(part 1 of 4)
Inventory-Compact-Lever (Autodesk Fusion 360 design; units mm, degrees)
parameter "FrameLength" = 640 comment "Fixed existing outer length"
parameter "FrameWidth" = 190 comment "Fixed existing outer width"
parameter "FrameHeight" = 110 comment "Fixed existing height"
parameter "PivotHeight" = 65 comment "Above frame center"
parameter "LeverTravel" = 100 comment "Stable endpoint to endpoint"
parameter "PrintClearance" = 0.3 comment "Prototype diametral running clearance"
base_mesh_feature "Base Mesh Feature"
ground "Pin1"
work_plane "WorkPlane1" AlongDistance -36 ExtraOffset 0
sketch "Flat load-bearing plate" plane through (-36, 0, 0) normal (1, 0, 0) x axis (0, 0, -1)
  line L1 (-33, -55) -> (-33, -75)
  line L2 (2, -55) -> (-33, -55)
  line L3 (2, 55) -> (2, -55)
  line L4 (-33, 55) -> (2, 55)
  line L5 (-33, 75) -> (-33, 55)
  line L6 (-57, 75) -> (-33, 75)
  line L7 (-57, 32) -> (-57, 75)
  line L8 (-86, 26) -> (-57, 32)
  line L9 (-86, -26) -> (-86, 26)
  line L10 (-57, -32) -> (-86, -26)
  line L11 (-57, -75) -> (-57, -32)
  line L12 (-33, -75) -> (-57, -75)
extrude "Extrude1" new body sketch "Flat load-bearing plate" along normal blind 12
work_plane "WorkPlane2" AlongDistance -37 ExtraOffset 0
sketch "Replaceable bushing seat" plane through (-37, 0, 0) normal (1, 0, 0) x axis (0, 0, -1)
  circle C1 centre (-65, 0) radius 10.15
extrude "Extrude2" cut sketch "Replaceable bushing seat" along normal blind 14
work_plane "WorkPlane3" AlongDistance -37 ExtraOffset 0
sketch "Follower pivot bolt" plane through (-37, 0, 0) normal (1, 0, 0) x axis (0, 0, -1)
  circle C1 centre (-12, -35) radius 2.7
extrude "Extrude3" cut sketch "Follower pivot bolt" along normal blind 14
work_plane "WorkPlane4" AlongDistance -76 ExtraOffset 0
sketch "M5 rail mounting bore" plane through (0, -76, 0) normal (0, 1, 0) x axis (1, 0, 0)
  circle C1 centre (-30, -45) radius 2.7
extrude "Extrude4" cut sketch "M5 rail mounting bore" along normal blind 22
work_plane "WorkPlane5" AlongDistance -55 ExtraOffset 0
sketch "Rail screw tool and washer access" plane through (0, -55, 0) normal (0, 1, 0) x axis (1, 0, 0)
  circle C1 centre (-30, -45) radius 5.3
extrude "Extrude5" cut sketch "Rail screw tool and washer access" along normal blind 12
work_plane "WorkPlane6" AlongDistance 54 ExtraOffset 0
sketch "M5 rail mounting bore (1)" plane through (0, 54, 0) normal (0, 1, 0) x axis (1, 0, 0)
  circle C1 centre (-30, -45) radius 2.7
extrude "Extrude6" cut sketch "M5 rail mounting bore (1)" along normal blind 22
work_plane "WorkPlane7" AlongDistance 43 ExtraOffset 0
sketch "Rail screw tool and washer access (1)" plane through (0, 43, 0) normal (0, 1, 0) x axis (1, 0, 0)
  circle C1 centre (-30, -45) radius 5.3
extrude "Extrude7" cut sketch "Rail screw tool and washer access (1)" along normal blind 12
work_plane "WorkPlane8" AlongDistance -37 ExtraOffset 0
sketch "Spring crossblock attachment" plane through (-37, 0, 0) normal (1, 0, 0) x axis (0, 0, -1)
  circle C1 centre (-44, -59) radius 1.7
extrude "Extrude8" cut sketch "Spring crossblock attachment" along normal blind 14
work_plane "WorkPlane9" AlongDistance -37 ExtraOffset 0
sketch "Spring crossblock attachment (1)" plane through (-37, 0, 0) normal (1, 0, 0) x axis (0, 0, -1)
  circle C1 centre (-44, -51) radius 1.7
extrude "Extrude9" cut sketch "Spring crossblock attachment (1)" along normal blind 14
work_plane "WorkPlane1" AlongDistance 24 ExtraOffset 0
sketch "Flat load-bearing plate" plane through (24, 0, 0) normal (1, 0, 0) x axis (0, 0, -1)
  line L1 (-33, -55) -> (-33, -75)
  line L2 (2, -55) -> (-33, -55)
  line L3 (2, 55) -> (2, -55)
  line L4 (-33, 55) -> (2, 55)
  line L5 (-33, 75) -> (-33, 55)
  line L6 (-57, 75) -> (-33, 75)
  line L7 (-57, 32) -> (-57, 75)
  line L8 (-86, 26) -> (-57, 32)
  line L9 (-86, -26) -> (-86, 26)
  line L10 (-57, -32) -> (-86, -26)
  line L11 (-57, -75) -> (-57, -32)
  line L12 (-33, -75) -> (-57, -75)
extrude "Extrude1" new body sketch "Flat load-bearing plate" along normal blind 12
work_plane "WorkPlane2" AlongDistance 23 ExtraOffset 0
sketch "Replaceable bushing seat" plane through (23, 0, 0) normal (1, 0, 0) x axis (0, 0, -1)
  circle C1 centre (-65, 0) radius 10.15
extrude "Extrude2" cut sketch "Replaceable bushing seat" along normal blind 14
work_plane "WorkPlane3" AlongDistance 23 ExtraOffset 0
sketch "Follower pivot bolt" plane through (23, 0, 0) normal (1, 0, 0) x axis (0, 0, -1)
  circle C1 centre (-12, -35) radius 2.7
extrude "Extrude3" cut sketch "Follower pivot bolt" along normal blind 14
work_plane "WorkPlane4" AlongDistance -76 ExtraOffset 0
sketch "M5 rail mounting bore" plane through (0, -76, 0) normal (0, 1, 0) x axis (1, 0, 0)
  circle C1 centre (30, -45) radius 2.7
extrude "Extrude4" cut sketch "M5 rail mounting bore" along normal blind 22
work_plane "WorkPlane5" AlongDistance -55 ExtraOffset 0
sketch "Rail screw tool and washer access" plane through (0, -55, 0) normal (0, 1, 0) x axis (1, 0, 0)
  circle C1 centre (30, -45) radius 5.3
extrude "Extrude5" cut sketch "Rail screw tool and washer access" along normal blind 12
work_plane "WorkPlane6" AlongDistance 54 ExtraOffset 0
sketch "M5 rail mounting bore (1)" plane through (0, 54, 0) normal (0, 1, 0) x axis (1, 0, 0)
  circle C1 centre (30, -45) radius 2.7
extrude "Extrude6" cut sketch "M5 rail mounting bore (1)" along normal blind 22
work_plane "WorkPlane7" AlongDistance 43 ExtraOffset 0
sketch "Rail screw tool and washer access (1)" plane through (0, 43, 0) normal (0, 1, 0) x axis (1, 0, 0)
  circle C1 centre (30, -45) radius 5.3
extrude "Extrude7" cut sketch "Rail screw tool and washer access (1)" along normal blind 12
work_plane "WorkPlane8" AlongDistance 23 ExtraOffset 0
sketch "Spring crossblock attachment" plane through (23, 0, 0) normal (1, 0, 0) x axis (0, 0, -1)
  circle C1 centre (-44, -59) radius 1.7
extrude "Extrude8" cut sketch "Spring crossblock attachment" along normal blind 14
work_plane "WorkPlane9" AlongDistance 23 ExtraOffset 0
sketch "Spring crossblock attachment (1)" plane through (23, 0, 0) normal (1, 0, 0) x axis (0, 0, -1)
  circle C1 centre (-44, -51) radius 1.7
extrude "Extrude9" cut sketch "Spring crossblock attachment (1)" along normal blind 14
work_plane "WorkPlane1" AlongDistance -36 ExtraOffset 0
sketch "Replaceable journal body" plane through (-36, 0, 0) normal (1, 0, 0) x axis (0, 0, -1)
  circle C1 centre (-65, 0) radius 10.05
extrude "Extrude1" new body sketch "Replaceable journal body" along normal blind 12 bodies "P03 Left flanged journal bush"
work_plane "WorkPlane2" AlongDistance -37.2 ExtraOffset 0
sketch "Axial thrust flange" plane through (-37.2, 0, 0) normal (1, 0, 0) x axis (0, 0, -1)
  circle C1 centre (-65, 0) radius 12.75
extrude "Extrude2" add sketch "Axial thrust flange" along normal blind 1.2
work_plane "WorkPlane3" AlongDistance -38 ExtraOffset 0
sketch "Running journal bore" plane through (-38, 0, 0) normal (1, 0, 0) x axis (0, 0, -1)
  circle C1 centre (-65, 0) radius 6.15
extrude "Extrude3" cut sketch "Running journal bore" along normal blind 15
work_plane "WorkPlane1" AlongDistance 24 ExtraOffset 0
sketch "Replaceable journal body" plane through (24, 0, 0) normal (1, 0, 0) x axis (0, 0, -1)
  circle C1 centre (-65, 0) radius 10.05
extrude "Extrude1" new body sketch "Replaceable journal body" along normal blind 12 bodies "P04 Right flanged journal bush"
work_plane "WorkPlane2" AlongDistance 36 ExtraOffset 0
sketch "Axial thrust flange" plane through (36, 0, 0) normal (1, 0, 0) x axis (0, 0, -1)
  circle C1 centre (-65, 0) radius 12.75
extrude "Extrude2" add sketch "Axial thrust flange" along normal blind 1.2
work_plane "WorkPlane3" AlongDistance 23 ExtraOffset 0
sketch "Running journal bore" plane through (23, 0, 0) normal (1, 0, 0) x axis (0, 0, -1)
  circle C1 centre (-65, 0) radius 6.15
extrude "Extrude3" cut sketch "Running journal bore" along normal blind 15
work_plane "WorkPlane1" AlongDistance -37.35 ExtraOffset 0
sketch "Continuous 12 mm journals" plane through (-37.35, 0, 0) normal (1, 0, 0) x axis (0, 0, -1)
  circle C1 centre (-65, 0) radius 6
extrude "Extrude1" new body sketch "Continuous 12 mm journals" along normal blind 74.7 bodies "P05 Shaft lower half"
work_plane "WorkPlane2" AlongDistance -23.8 ExtraOffset 0
sketch "16 mm structural shaft" plane through (-23.8, 0, 0) normal (1, 0, 0) x axis (0, 0, -1)
  circle C1 centre (-65, 0) radius 8
extrude "Extrude2" add sketch "16 mm structural shaft" along normal blind 47.6
work_plane "WorkPlane3" AlongDistance -23.9 ExtraOffset 0
sketch "D-flat torque key" plane through (-23.9, 0, 0) normal (1, 0, 0) x axis (0, 0, -1)
  line L1 (-56, 9) -> (-56, 6.5)
  line L2 (-74, 9) -> (-56, 9)
  line L3 (-74, 6.5) -> (-74, 9)
  line L4 (-56, 6.5) -> (-74, 6.5)
extrude "Extrude3" cut sketch "D-flat torque key" along normal blind 47.8
work_plane "WorkPlane4" AlongDistance 37.35 ExtraOffset 0
sketch "Integral axial shoulder" plane through (37.35, 0, 0) normal (1, 0, 0) x axis (0, 0, -1)
  circle C1 centre (-65, 0) radius 10
extrude "Extrude4" add sketch "Integral axial shoulder" along normal blind 3
work_plane "WorkPlane5" AlongDistance 40.35 ExtraOffset 0
sketch "Sensor drive stub" plane through (40.35, 0, 0) normal (1, 0, 0) x axis (0, 0, -1)
  circle C1 centre (-65, 0) radius 4
extrude "Extrude5" add sketch "Sensor drive stub" along normal blind 10
work_plane "WorkPlane6" AlongDistance 40.25 ExtraOffset 0
sketch "Sensor drive flat" plane through (40.25, 0, 0) normal (1, 0, 0) x axis (0, 0, -1)
  line L1 (-60, 5) -> (-60, 3.2)
  line L2 (-70, 5) -> (-60, 5)
  line L3 (-70, 3.2) -> (-70, 5)
  line L4 (-60, 3.2) -> (-70, 3.2)
extrude "Extrude6" cut sketch "Sensor drive flat" along normal blind 10.25
work_plane "WorkPlane7" AlongDistance -37.45 ExtraOffset 0
sketch "M3 heat-set end retention" plane through (-37.45, 0, 0) normal (1, 0, 0) x axis (0, 0, -1)
  circle C1 centre (-65, 0) radius 2
extrude "Extrude7" cut sketch "M3 heat-set end retention" along normal blind 6.8
work_plane "WorkPlane1" AlongDistance -39.35 ExtraOffset 0
sketch "Axial cap" plane through (-39.35, 0, 0) normal (1, 0, 0) x axis (0, 0, -1)
  circle C1 centre (-65, 0) radius 10
extrude "Extrude1" new body sketch "Axial cap" along normal blind 2 bodies "P06 Shaft retaining cap"
work_plane "WorkPlane2" AlongDistance -39.5 ExtraOffset 0
sketch "M3 cap screw" plane through (-39.5, 0, 0) normal (1, 0, 0) x axis (0, 0, -1)
  circle C1 centre (-65, 0) radius 1.7
extrude "Extrude2" cut sketch "M3 cap screw" along normal blind 2.4
work_plane "WorkPlane1" AlongDistance -7 ExtraOffset 0
sketch "Main lever hub" plane through (-7, 0, 0) normal (1, 0, 0) x axis (0, 0, -1)
  circle C1 centre (-65, 0) radius 22
extrude "Extrude1" new body sketch "Main lever hub" along normal blind 14 bodies "P07 Integral lever rotor and cam carrier"
work_plane "WorkPlane2" AlongDistance -7 ExtraOffset 0
sketch "Continuous reinforced lever stem" plane through (-7, 0, 0) normal (1, 0, 0) x axis (0, 0, -1)
  line L1 (-60, 14) -> (-60, -14)
  line L2 (-95, 11) -> (-60, 14)
  line L3 (-150, 7) -> (-95, 11)
  line L4 (-195, 7) -> (-150, 7)
  line L5 (-195, -7) -> (-195, 7)
  line L6 (-150, -7) -> (-195, -7)
  line L7 (-95, -11) -> (-150, -7)
  line L8 (-60, -14) -> (-95, -11)
extrude "Extrude2" add sketch "Continuous reinforced lever stem" along normal blind 14
work_plane "WorkPlane3" AlongDistance -7 ExtraOffset 0
sketch "Integrated cam carrier fan" plane through (-7, 0, 0) normal (1, 0, 0) x axis (0, 0, -1)
  line L1 (-44.5, 35.507) -> (-65, 0)
  line L2 (-42.6698, 34.3855) -> (-44.5, 35.507)
  line L3 (-40.9008, 33.1697) -> (-42.6698, 34.3855)
  line L4 (-39.1979, 31.863) -> (-40.9008, 33.1697)
  line L5 (-37.5656, 30.4689) -> (-39.1979, 31.863)
  line L6 (-36.0086, 28.9914) -> (-37.5656, 30.4689)
  line L7 (-34.5311, 27.4344) -> (-36.0086, 28.9914)
  line L8 (-33.137, 25.8021) -> (-34.5311, 27.4344)
  line L9 (-31.8303, 24.0992) -> (-33.137, 25.8021)
  line L10 (-30.6145, 22.3302) -> (-31.8303, 24.0992)
  line L11 (-29.493, 20.5) -> (-30.6145, 22.3302)
  line L12 (-28.4687, 18.6136) -> (-29.493, 20.5)
  line L13 (-27.5446, 16.6762) -> (-28.4687, 18.6136)
  line L14 (-26.7232, 14.6931) -> (-27.5446, 16.6762)
  line L15 (-26.0067, 12.6697) -> (-26.7232, 14.6931)
  line L16 (-25.397, 10.6116) -> (-26.0067, 12.6697)
  line L17 (-24.8959, 8.5244) -> (-25.397, 10.6116)
  line L18 (-24.5048, 6.4138) -> (-24.8959, 8.5244)
  line L19 (-24.2246, 4.2857) -> (-24.5048, 6.4138)
  line L20 (-24.0562, 2.1458) -> (-24.2246, 4.2857)
  line L21 (-24, 0) -> (-24.0562, 2.1458)
  line L22 (-24.0562, -2.1458) -> (-24, 0)
  line L23 (-24.2246, -4.2857) -> (-24.0562, -2.1458)
  line L24 (-24.5048, -6.4138) -> (-24.2246, -4.2857)
  line L25 (-24.8959, -8.5244) -> (-24.5048, -6.4138)
  line L26 (-25.397, -10.6116) -> (-24.8959, -8.5244)
  line L27 (-26.0067, -12.6697) -> (-25.397, -10.6116)
  line L28 (-26.7232, -14.6931) -> (-26.0067, -12.6697)
  line L29 (-27.5446, -16.6762) -> (-26.7232, -14.6931)
  line L30 (-28.4687, -18.6136) -> (-27.5446, -16.6762)
  line L31 (-29.493, -20.5) -> (-28.4687, -18.6136)
  line L32 (-30.6145, -22.3302) -> (-29.493, -20.5)
  line L33 (-31.8303, -24.0992) -> (-30.6145, -22.3302)
  line L34 (-33.137, -25.8021) -> (-31.8303, -24.0992)
  line L35 (-34.5311, -27.4344) -> (-33.137, -25.8021)
  line L36 (-36.0086, -28.9914) -> (-34.5311, -27.4344)
  line L37 (-37.5656, -30.4689) -> (-36.0086, -28.9914)
  line L38 (-39.1979, -31.863) -> (-37.5656, -30.4689)
  line L39 (-40.9008, -33.1697) -> (-39.1979, -31.863)
  line L40 (-42.6698, -34.3855) -> (-40.9008, -33.1697)
  line L41 (-44.5, -35.507) -> (-42.6698, -34.3855)
  line L42 (-65, 0) -> (-44.5, -35.507)
extrude "Extrude3" add sketch "Integrated cam carrier fan" along normal blind 14
work_plane "WorkPlane4" AlongDistance -23.6 ExtraOffset 0
sketch "Integral axial locating hub" plane through (-23.6, 0, 0) normal (1, 0, 0) x axis (0, 0, -1)
  circle C1 centre (-65, 0) radius 10
work_plane "WorkPlane5" AlongDistance -24 ExtraOffset 0
sketch "D shaft socket" plane through (-24, 0, 0) normal (1, 0, 0) x axis (0, 0, -1)
  line L1 (-69.6247, 6.65) -> (-60.3753, 6.65)
  arc A1 centre (-65, 0) radius 8.1 clockwise from (-60.3753, 6.65) to (-69.6247, 6.65)
extrude "Extrude5" cut sketch "D shaft socket" along normal blind 48
work_plane "WorkPlane6" AlongDistance 0.3 ExtraOffset 0
sketch "Cam M3 insert pocket" plane through (0.3, 0, 0) normal (1, 0, 0) x axis (0, 0, -1)
  circle C1 centre (-39.5442, 25.4558) radius 2
extrude "Extrude6" cut sketch "Cam M3 insert pocket" along normal blind 6.8
work_plane "WorkPlane7" AlongDistance 0.3 ExtraOffset 0
sketch "Cam M3 insert pocket (1)" plane through (0.3, 0, 0) normal (1, 0, 0) x axis (0, 0, -1)
  circle C1 centre (-29, 0) radius 2
extrude "Extrude7" cut sketch "Cam M3 insert pocket (1)" along normal blind 6.8
work_plane "WorkPlane8" AlongDistance 0.3 ExtraOffset 0
sketch "Cam M3 insert pocket (2)" plane through (0.3, 0, 0) normal (1, 0, 0) x axis (0, 0, -1)
  circle C1 centre (-39.5442, -25.4558) radius 2
extrude "Extrude8" cut sketch "Cam M3 insert pocket (2)" along normal blind 6.8
work_plane "WorkPlane9" AlongDistance -8 ExtraOffset 0
sketch "Grip through bolt" plane through (-8, 0, 0) normal (1, 0, 0) x axis (0, 0, -1)
  circle C1 centre (-180, 0) radius 1.7
extrude "Extrude9" cut sketch "Grip through bolt" along normal blind 16
work_plane "WorkPlane10" AlongDistance -8 ExtraOffset 0
sketch "Grip through bolt (1)" plane through (-8, 0, 0) normal (1, 0, 0) x axis (0, 0, -1)
  circle C1 centre (-190, 0) radius 1.7
extrude "Extrude10" cut sketch "Grip through bolt (1)" along normal blind 16
work_plane "WorkPlane1" AlongDistance 7 ExtraOffset 0
sketch "Roller compensated replaceable cam" plane through (7, 0, 0) normal (1, 0, 0) x axis (0, 0, -1)
  line L1 (-39.4967, 42.2602) -> (-39.6212, 42.3096)
  line L2 (-39.3834, 42.211) -> (-39.4967, 42.2602)
  line L3 (-39.2796, 42.1617) -> (-39.3834, 42.211)
  line L4 (-39.1836, 42.1119) -> (-39.2796, 42.1617)
  line L5 (-39.0932, 42.0608) -> (-39.1836, 42.1119)
  line L6 (-39.0065, 42.0075) -> (-39.0932, 42.0608)
  line L7 (-38.9215, 41.9508) -> (-39.0065, 42.0075)
  line L8 (-38.8363, 41.8895) -> (-38.9215, 41.9508)
  line L9 (-38.7492, 41.8219) -> (-38.8363, 41.8895)
  line L10 (-38.6586, 41.7465) -> (-38.7492, 41.8219)
  line L11 (-38.5633, 41.6619) -> (-38.6586, 41.7465)
  line L12 (-38.4623, 41.5665) -> (-38.5633, 41.6619)
  line L13 (-38.3549, 41.459) -> (-38.4623, 41.5665)
  line L14 (-38.2404, 41.3384) -> (-38.3549, 41.459)
  line L15 (-38.1184, 41.204) -> (-38.2404, 41.3384)
  line L16 (-37.9886, 41.055) -> (-38.1184, 41.204)
  line L17 (-37.8508, 40.8913) -> (-37.9886, 41.055)
  line L18 (-37.7045, 40.7127) -> (-37.8508, 40.8913)
  line L19 (-37.5496, 40.5196) -> (-37.7045, 40.7127)
  line L20 (-37.3856, 40.3123) -> (-37.5496, 40.5196)
  line L21 (-37.2122, 40.0915) -> (-37.3856, 40.3123)
  line L22 (-37.0289, 39.858) -> (-37.2122, 40.0915)
  line L23 (-36.8353, 39.6128) -> (-37.0289, 39.858)
  line L24 (-36.6306, 39.3571) -> (-36.8353, 39.6128)
  line L25 (-36.4145, 39.0923) -> (-36.6306, 39.3571)
  line L26 (-36.1865, 38.82) -> (-36.4145, 39.0923)
  line L27 (-35.9461, 38.5417) -> (-36.1865, 38.82)
  line L28 (-35.6932, 38.2594) -> (-35.9461, 38.5417)
  line L29 (-35.4277, 37.9751) -> (-35.6932, 38.2594)
  line L30 (-35.15, 37.6908) -> (-35.4277, 37.9751)
  line L31 (-34.8607, 37.4087) -> (-35.15, 37.6908)
  line L32 (-34.5606, 37.1307) -> (-34.8607, 37.4087)
  line L33 (-34.2512, 36.859) -> (-34.5606, 37.1307)
  line L34 (-33.934, 36.5953) -> (-34.2512, 36.859)
  line L35 (-33.6109, 36.341) -> (-33.934, 36.5953)
  line L36 (-33.2841, 36.0975) -> (-33.6109, 36.341)
  line L37 (-32.9558, 35.8655) -> (-33.2841, 36.0975)
  line L38 (-32.6282, 35.6454) -> (-32.9558, 35.8655)
  line L39 (-32.3036, 35.4375) -> (-32.6282, 35.6454)
  line L40 (-31.984, 35.2415) -> (-32.3036, 35.4375)
  line L41 (-31.6712, 35.057) -> (-31.984, 35.2415)
  line L42 (-31.3671, 34.8833) -> (-31.6712, 35.057)
  line L43 (-31.073, 34.7197) -> (-31.3671, 34.8833)
  line L44 (-30.7902, 34.5655) -> (-31.073, 34.7197)
  line L45 (-30.52, 34.4197) -> (-30.7902, 34.5655)
  line L46 (-30.263, 34.2816) -> (-30.52, 34.4197)
  line L47 (-30.0201, 34.1506) -> (-30.263, 34.2816)
  line L48 (-29.7919, 34.0259) -> (-30.0201, 34.1506)
  line L49 (-29.5787, 33.9071) -> (-29.7919, 34.0259)
  line L50 (-29.3807, 33.7939) -> (-29.5787, 33.9071)
  line L51 (-29.1982, 33.6858) -> (-29.3807, 33.7939)
  line L52 (-29.0309, 33.5827) -> (-29.1982, 33.6858)
  line L53 (-28.8786, 33.4843) -> (-29.0309, 33.5827)
  line L54 (-28.7406, 33.3906) -> (-28.8786, 33.4843)
  line L55 (-28.6164, 33.3013) -> (-28.7406, 33.3906)
  line L56 (-28.5047, 33.2161) -> (-28.6164, 33.3013)
  line L57 (-28.4046, 33.1346) -> (-28.5047, 33.2161)
  line L58 (-28.3144, 33.0563) -> (-28.4046, 33.1346)
  line L59 (-28.2327, 32.9802) -> (-28.3144, 33.0563)
  line L60 (-28.1577, 32.9052) -> (-28.2327, 32.9802)
  line L61 (-28.0879, 32.8301) -> (-28.1577, 32.9052)
  line L62 (-28.0214, 32.7532) -> (-28.0879, 32.8301)
  line L63 (-27.9569, 32.6728) -> (-28.0214, 32.7532)
  line L64 (-27.893, 32.5869) -> (-27.9569, 32.6728)
  line L65 (-27.8285, 32.4936) -> (-27.893, 32.5869)
  line L66 (-27.7627, 32.3911) -> (-27.8285, 32.4936)
  line L67 (-27.6947, 32.2776) -> (-27.7627, 32.3911)
  line L68 (-27.6241, 32.1514) -> (-27.6947, 32.2776)
  line L69 (-27.5507, 32.0113) -> (-27.6241, 32.1514)
  line L70 (-27.4742, 31.8562) -> (-27.5507, 32.0113)
  line L71 (-27.3945, 31.6853) -> (-27.4742, 31.8562)
  line L72 (-27.3113, 31.4981) -> (-27.3945, 31.6853)
  line L73 (-27.2245, 31.2943) -> (-27.3113, 31.4981)
  line L74 (-27.1338, 31.074) -> (-27.2245, 31.2943)
  line L75 (-27.0388, 30.8373) -> (-27.1338, 31.074)
  line L76 (-26.939, 30.5847) -> (-27.0388, 30.8373)
  line L77 (-26.8337, 30.3166) -> (-26.939, 30.5847)
  line L78 (-26.7223, 30.034) -> (-26.8337, 30.3166)
  line L79 (-26.6038, 29.7375) -> (-26.7223, 30.034)
  line L80 (-26.4775, 29.4284) -> (-26.6038, 29.7375)
  line L81 (-26.3424, 29.1079) -> (-26.4775, 29.4284)
  line L82 (-26.1977, 28.7772) -> (-26.3424, 29.1079)
  line L83 (-26.0425, 28.4382) -> (-26.1977, 28.7772)
  line L84 (-25.8761, 28.0925) -> (-26.0425, 28.4382)
  line L85 (-25.6981, 27.7422) -> (-25.8761, 28.0925)
  line L86 (-25.5084, 27.3893) -> (-25.6981, 27.7422)
  line L87 (-25.3069, 27.0362) -> (-25.5084, 27.3893)
  line L88 (-25.0943, 26.6851) -> (-25.3069, 27.0362)
  line L89 (-24.8713, 26.3382) -> (-25.0943, 26.6851)
  line L90 (-24.6392, 25.9976) -> (-24.8713, 26.3382)
  line L91 (-24.3995, 25.6653) -> (-24.6392, 25.9976)
  line L92 (-24.1539, 25.3428) -> (-24.3995, 25.6653)
  line L93 (-23.9045, 25.0314) -> (-24.1539, 25.3428)
  line L94 (-23.6532, 24.7321) -> (-23.9045, 25.0314)
  line L95 (-23.4022, 24.4455) -> (-23.6532, 24.7321)
  line L96 (-23.1534, 24.1718) -> (-23.4022, 24.4455)
  line L97 (-22.9088, 23.9111) -> (-23.1534, 24.1718)
  line L98 (-22.6701, 23.6631) -> (-22.9088, 23.9111)
  line L99 (-22.4387, 23.4276) -> (-22.6701, 23.6631)
  line L100 (-22.2162, 23.204) -> (-22.4387, 23.4276)
  line L101 (-22.0036, 22.9918) -> (-22.2162, 23.204)
  line L102 (-21.8021, 22.7907) -> (-22.0036, 22.9918)
  line L103 (-21.6123, 22.6001) -> (-21.8021, 22.7907)
  line L104 (-21.435, 22.4197) -> (-21.6123, 22.6001)
  line L105 (-21.2706, 22.2491) -> (-21.435, 22.4197)
  line L106 (-21.1193, 22.088) -> (-21.2706, 22.2491)
  line L107 (-20.9813, 21.9362) -> (-21.1193, 22.088)
  line L108 (-20.8565, 21.7934) -> (-20.9813, 21.9362)
  line L109 (-20.7443, 21.6594) -> (-20.8565, 21.7934)
  line L110 (-20.6444, 21.5337) -> (-20.7443, 21.6594)
  line L111 (-20.556, 21.4159) -> (-20.6444, 21.5337)
  line L112 (-20.478, 21.3055) -> (-20.556, 21.4159)
  line L113 (-20.4094, 21.2014) -> (-20.478, 21.3055)
  line L114 (-20.349, 21.1027) -> (-20.4094, 21.2014)
  line L115 (-20.2954, 21.0079) -> (-20.349, 21.1027)
  line L116 (-20.2475, 20.9154) -> (-20.2954, 21.0079)
  line L117 (-20.2039, 20.8234) -> (-20.2475, 20.9154)
  line L118 (-20.1637, 20.7297) -> (-20.2039, 20.8234)
  line L119 (-20.126, 20.6321) -> (-20.1637, 20.7297)
  line L120 (-20.0901, 20.5286) -> (-20.126, 20.6321)
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extrude "Extrude1" new body sketch "Roller compensated replaceable cam" along normal blind 8 bodies "P08 Cam 7 gates - stable endpoints"
work_plane "WorkPlane2" AlongDistance 6.9 ExtraOffset 0
sketch "Cam screw clearance" plane through (6.9, 0, 0) normal (1, 0, 0) x axis (0, 0, -1)
  circle C1 centre (-39.5442, 25.4558) radius 1.7
extrude "Extrude2" cut sketch "Cam screw clearance" along normal blind 8.2
work_plane "WorkPlane3" AlongDistance 12 ExtraOffset 0
sketch "Cam head recess" plane through (12, 0, 0) normal (1, 0, 0) x axis (0, 0, -1)
  circle C1 centre (-39.5442, 25.4558) radius 3.1
extrude "Extrude3" cut sketch "Cam head recess" along normal blind 3.1
work_plane "WorkPlane4" AlongDistance 6.9 ExtraOffset 0
sketch "Cam screw clearance (1)" plane through (6.9, 0, 0) normal (1, 0, 0) x axis (0, 0, -1)
  circle C1 centre (-29, 0) radius 1.7
extrude "Extrude4" cut sketch "Cam screw clearance (1)" along normal blind 8.2
work_plane "WorkPlane5" AlongDistance 12 ExtraOffset 0
sketch "Cam head recess (1)" plane through (12, 0, 0) normal (1, 0, 0) x axis (0, 0, -1)
  circle C1 centre (-29, 0) radius 3.1
extrude "Extrude5" cut sketch "Cam head recess (1)" along normal blind 3.1
work_plane "WorkPlane6" AlongDistance 6.9 ExtraOffset 0
sketch "Cam screw clearance (2)" plane through (6.9, 0, 0) normal (1, 0, 0) x axis (0, 0, -1)
  circle C1 centre (-39.5442, -25.4558) radius 1.7
extrude "Extrude6" cut sketch "Cam screw clearance (2)" along normal blind 8.2
work_plane "WorkPlane7" AlongDistance 12 ExtraOffset 0
sketch "Cam head recess (2)" plane through (12, 0, 0) normal (1, 0, 0) x axis (0, 0, -1)
  circle C1 centre (-39.5442, -25.4558) radius 3.1
extrude "Extrude7" cut sketch "Cam head recess (2)" along normal blind 3.1
work_plane "WorkPlane1" AlongDistance 7 ExtraOffset 0
sketch "Roller compensated replaceable cam" plane through (7, 0, 0) normal (1, 0, 0) x axis (0, 0, -1)
  line L1 (-40.6423, 42.8316) -> (-40.8055, 42.9534)
  line L2 (-40.4783, 42.705) -> (-40.6423, 42.8316)
  line L3 (-40.3132, 42.5736) -> (-40.4783, 42.705)
  line L4 (-40.1469, 42.4372) -> (-40.3132, 42.5736)
  line L5 (-39.9791, 42.2958) -> (-40.1469, 42.4372)
  line L6 (-39.8097, 42.1493) -> (-39.9791, 42.2958)
  line L7 (-39.6386, 41.9977) -> (-39.8097, 42.1493)
  line L8 (-39.4656, 41.8411) -> (-39.6386, 41.9977)
  line L9 (-39.2906, 41.6794) -> (-39.4656, 41.8411)
  line L10 (-39.1134, 41.5128) -> (-39.2906, 41.6794)
  line L11 (-38.9338, 41.3413) -> (-39.1134, 41.5128)
  line L12 (-38.7519, 41.165) -> (-38.9338, 41.3413)
  line L13 (-38.5674, 40.9842) -> (-38.7519, 41.165)
  line L14 (-38.3803, 40.7991) -> (-38.5674, 40.9842)
  line L15 (-38.1904, 40.6097) -> (-38.3803, 40.7991)
  line L16 (-37.9976, 40.4164) -> (-38.1904, 40.6097)
  line L17 (-37.8019, 40.2195) -> (-37.9976, 40.4164)
  line L18 (-37.6031, 40.0191) -> (-37.8019, 40.2195)
  line L19 (-37.4011, 39.8157) -> (-37.6031, 40.0191)
  line L20 (-37.1958, 39.6094) -> (-37.4011, 39.8157)
  line L21 (-36.9872, 39.4008) -> (-37.1958, 39.6094)
  line L22 (-36.7753, 39.19) -> (-36.9872, 39.4008)
  line L23 (-36.5599, 38.9775) -> (-36.7753, 39.19)
  line L24 (-36.3411, 38.7636) -> (-36.5599, 38.9775)
  line L25 (-36.1189, 38.5488) -> (-36.3411, 38.7636)
  line L26 (-35.8933, 38.3333) -> (-36.1189, 38.5488)
  line L27 (-35.6644, 38.1177) -> (-35.8933, 38.3333)
  line L28 (-35.4322, 37.9021) -> (-35.6644, 38.1177)
  line L29 (-35.197, 37.6871) -> (-35.4322, 37.9021)
  line L30 (-34.9588, 37.473) -> (-35.197, 37.6871)
  line L31 (-34.7178, 37.2602) -> (-34.9588, 37.473)
  line L32 (-34.4743, 37.0489) -> (-34.7178, 37.2602)
  line L33 (-34.2286, 36.8395) -> (-34.4743, 37.0489)
  line L34 (-33.9808, 36.6322) -> (-34.2286, 36.8395)
  line L35 (-33.7314, 36.4274) -> (-33.9808, 36.6322)
  line L36 (-33.4806, 36.2252) -> (-33.7314, 36.4274)
  line L37 (-33.2289, 36.0258) -> (-33.4806, 36.2252)
  line L38 (-32.9765, 35.8294) -> (-33.2289, 36.0258)
  line L39 (-32.7239, 35.6361) -> (-32.9765, 35.8294)
  line L40 (-32.4714, 35.446) -> (-32.7239, 35.6361)
  line L41 (-32.2195, 35.259) -> (-32.4714, 35.446)
  line L42 (-31.9685, 35.0753) -> (-32.2195, 35.259)
  line L43 (-31.7188, 34.8948) -> (-31.9685, 35.0753)
  line L44 (-31.4708, 34.7175) -> (-31.7188, 34.8948)
  line L45 (-31.2249, 34.5432) -> (-31.4708, 34.7175)
  line L46 (-30.9813, 34.3719) -> (-31.2249, 34.5432)
  line L47 (-30.7405, 34.2034) -> (-30.9813, 34.3719)
  line L48 (-30.5027, 34.0377) -> (-30.7405, 34.2034)
  line L49 (-30.2682, 33.8746) -> (-30.5027, 34.0377)
  line L50 (-30.0373, 33.7139) -> (-30.2682, 33.8746)
  line L51 (-29.8103, 33.5555) -> (-30.0373, 33.7139)
  line L52 (-29.5875, 33.3992) -> (-29.8103, 33.5555)
  line L53 (-29.3689, 33.2448) -> (-29.5875, 33.3992)
  line L54 (-29.1548, 33.0923) -> (-29.3689, 33.2448)
  line L55 (-28.9455, 32.9414) -> (-29.1548, 33.0923)
  line L56 (-28.7409, 32.7921) -> (-28.9455, 32.9414)
  line L57 (-28.5413, 32.644) -> (-28.7409, 32.7921)
  line L58 (-28.3468, 32.4972) -> (-28.5413, 32.644)
  line L59 (-28.1574, 32.3515) -> (-28.3468, 32.4972)
  line L60 (-27.9732, 32.2068) -> (-28.1574, 32.3515)
  line L61 (-27.7942, 32.0628) -> (-27.9732, 32.2068)
  line L62 (-27.6204, 31.9196) -> (-27.7942, 32.0628)
  line L63 (-27.4518, 31.7769) -> (-27.6204, 31.9196)
  line L64 (-27.2884, 31.6347) -> (-27.4518, 31.7769)
  line L65 (-27.1301, 31.4927) -> (-27.2884, 31.6347)
  line L66 (-26.9767, 31.351) -> (-27.1301, 31.4927)
  line L67 (-26.8282, 31.2092) -> (-26.9767, 31.351)
  line L68 (-26.6843, 31.0673) -> (-26.8282, 31.2092)
  line L69 (-26.545, 30.925) -> (-26.6843, 31.0673)
  line L70 (-26.4101, 30.7822) -> (-26.545, 30.925)
  line L71 (-26.2793, 30.6387) -> (-26.4101, 30.7822)
  line L72 (-26.1524, 30.4942) -> (-26.2793, 30.6387)
  line L73 (-26.0293, 30.3485) -> (-26.1524, 30.4942)
  line L74 (-25.9096, 30.2013) -> (-26.0293, 30.3485)
  line L75 (-25.7932, 30.0524) -> (-25.9096, 30.2013)
  line L76 (-25.6797, 29.9015) -> (-25.7932, 30.0524)
  line L77 (-25.5691, 29.7482) -> (-25.6797, 29.9015)
  line L78 (-25.461, 29.5923) -> (-25.5691, 29.7482)
  line L79 (-25.3553, 29.4334) -> (-25.461, 29.5923)
  line L80 (-25.2517, 29.2713) -> (-25.3553, 29.4334)
  line L81 (-25.15, 29.1057) -> (-25.2517, 29.2713)
  line L82 (-25.0502, 28.9363) -> (-25.15, 29.1057)
  line L83 (-24.9519, 28.7628) -> (-25.0502, 28.9363)
  line L84 (-24.855, 28.5849) -> (-24.9519, 28.7628)
  line L85 (-24.7595, 28.4024) -> (-24.855, 28.5849)
  line L86 (-24.665, 28.2152) -> (-24.7595, 28.4024)
  line L87 (-24.5716, 28.023) -> (-24.665, 28.2152)
  line L88 (-24.4791, 27.8257) -> (-24.5716, 28.023)
  line L89 (-24.3873, 27.6231) -> (-24.4791, 27.8257)
  line L90 (-24.2961, 27.4152) -> (-24.3873, 27.6231)
  line L91 (-24.2054, 27.2019) -> (-24.2961, 27.4152)
  line L92 (-24.115, 26.9832) -> (-24.2054, 27.2019)
  line L93 (-24.0247, 26.7591) -> (-24.115, 26.9832)
  line L94 (-23.9346, 26.5296) -> (-24.0247, 26.7591)
  line L95 (-23.8442, 26.2947) -> (-23.9346, 26.5296)
  line L96 (-23.7536, 26.0546) -> (-23.8442, 26.2947)
  line L97 (-23.6625, 25.8094) -> (-23.7536, 26.0546)
  line L98 (-23.5707, 25.5592) -> (-23.6625, 25.8094)
  line L99 (-23.478, 25.3041) -> (-23.5707, 25.5592)
  line L100 (-23.3842, 25.0444) -> (-23.478, 25.3041)
  line L101 (-23.2891, 24.7802) -> (-23.3842, 25.0444)
  line L102 (-23.1926, 24.5118) -> (-23.2891, 24.7802)
  line L103 (-23.0943, 24.2394) -> (-23.1926, 24.5118)
  line L104 (-22.9942, 23.9633) -> (-23.0943, 24.2394)
  line L105 (-22.8919, 23.6838) -> (-22.9942, 23.9633)
  line L106 (-22.7873, 23.4012) -> (-22.8919, 23.6838)
  line L107 (-22.6803, 23.1157) -> (-22.7873, 23.4012)
  line L108 (-22.5706, 22.8278) -> (-22.6803, 23.1157)
  line L109 (-22.4581, 22.5379) -> (-22.5706, 22.8278)
  line L110 (-22.3428, 22.2461) -> (-22.4581, 22.5379)
  line L111 (-22.2245, 21.953) -> (-22.3428, 22.2461)
  line L112 (-22.1031, 21.659) -> (-22.2245, 21.953)
  line L113 (-21.9788, 21.3644) -> (-22.1031, 21.659)
  line L114 (-21.8513, 21.0696) -> (-21.9788, 21.3644)
  line L115 (-21.7209, 20.7751) -> (-21.8513, 21.0696)
  line L116 (-21.5876, 20.4811) -> (-21.7209, 20.7751)
  line L117 (-21.4516, 20.1882) -> (-21.5876, 20.4811)
  line L118 (-21.3129, 19.8966) -> (-21.4516, 20.1882)
  line L119 (-21.1718, 19.6067) -> (-21.3129, 19.8966)
  line L120 (-21.0286, 19.3189) -> (-21.1718, 19.6067)
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extrude "Extrude1" new body sketch "Roller compensated replaceable cam" along normal blind 8 bodies "P08 Cam 5 gates - stable endpoints"
work_plane "WorkPlane2" AlongDistance 6.9 ExtraOffset 0
sketch "Cam screw clearance" plane through (6.9, 0, 0) normal (1, 0, 0) x axis (0, 0, -1)
  circle C1 centre (-39.5442, 25.4558) radius 1.7
extrude "Extrude2" cut sketch "Cam screw clearance" along normal blind 8.2
work_plane "WorkPlane3" AlongDistance 12 ExtraOffset 0
sketch "Cam head recess" plane through (12, 0, 0) normal (1, 0, 0) x axis (0, 0, -1)
  circle C1 centre (-39.5442, 25.4558) radius 3.1
extrude "Extrude3" cut sketch "Cam head recess" along normal blind 3.1
work_plane "WorkPlane4" AlongDistance 6.9 ExtraOffset 0
sketch "Cam screw clearance (1)" plane through (6.9, 0, 0) normal (1, 0, 0) x axis (0, 0, -1)
  circle C1 centre (-29, 0) radius 1.7
extrude "Extrude4" cut sketch "Cam screw clearance (1)" along normal blind 8.2
work_plane "WorkPlane5" AlongDistance 12 ExtraOffset 0
sketch "Cam head recess (1)" plane through (12, 0, 0) normal (1, 0, 0) x axis (0, 0, -1)
  circle C1 centre (-29, 0) radius 3.1
extrude "Extrude5" cut sketch "Cam head recess (1)" along normal blind 3.1
work_plane "WorkPlane6" AlongDistance 6.9 ExtraOffset 0
sketch "Cam screw clearance (2)" plane through (6.9, 0, 0) normal (1, 0, 0) x axis (0, 0, -1)
  circle C1 centre (-39.5442, -25.4558) radius 1.7
extrude "Extrude6" cut sketch "Cam screw clearance (2)" along normal blind 8.2
work_plane "WorkPlane7" AlongDistance 12 ExtraOffset 0
sketch "Cam head recess (2)" plane through (12, 0, 0) normal (1, 0, 0) x axis (0, 0, -1)
  circle C1 centre (-39.5442, -25.4558) radius 3.1
extrude "Extrude7" cut sketch "Cam head recess (2)" along normal blind 3.1
work_plane "WorkPlane1" AlongDistance 7 ExtraOffset 0
sketch "Roller compensated replaceable cam" plane through (7, 0, 0) normal (1, 0, 0) x axis (0, 0, -1)
  line L1 (-40.92, 42.0772) -> (-41.1325, 42.2273)
  line L2 (-40.7077, 41.9259) -> (-40.92, 42.0772)
  line L3 (-40.4956, 41.7734) -> (-40.7077, 41.9259)
  line L4 (-40.2838, 41.6199) -> (-40.4956, 41.7734)
  line L5 (-40.0721, 41.4654) -> (-40.2838, 41.6199)
  line L6 (-39.8606, 41.3098) -> (-40.0721, 41.4654)
  line L7 (-39.6492, 41.1532) -> (-39.8606, 41.3098)
  line L8 (-39.4381, 40.9957) -> (-39.6492, 41.1532)
  line L9 (-39.2271, 40.8372) -> (-39.4381, 40.9957)
  line L10 (-39.0163, 40.6779) -> (-39.2271, 40.8372)
  line L11 (-38.8057, 40.5176) -> (-39.0163, 40.6779)
  line L12 (-38.5952, 40.3566) -> (-38.8057, 40.5176)
  line L13 (-38.3849, 40.1947) -> (-38.5952, 40.3566)
  line L14 (-38.1747, 40.032) -> (-38.3849, 40.1947)
  line L15 (-37.9647, 39.8686) -> (-38.1747, 40.032)
  line L16 (-37.7549, 39.7045) -> (-37.9647, 39.8686)
  line L17 (-37.5452, 39.5397) -> (-37.7549, 39.7045)
  line L18 (-37.3357, 39.3742) -> (-37.5452, 39.5397)
  line L19 (-37.1263, 39.2081) -> (-37.3357, 39.3742)
  line L20 (-36.9171, 39.0413) -> (-37.1263, 39.2081)
  line L21 (-36.7081, 38.874) -> (-36.9171, 39.0413)
  line L22 (-36.4992, 38.7061) -> (-36.7081, 38.874)
  line L23 (-36.2905, 38.5376) -> (-36.4992, 38.7061)
  line L24 (-36.082, 38.3687) -> (-36.2905, 38.5376)
  line L25 (-35.8737, 38.1992) -> (-36.082, 38.3687)
  line L26 (-35.6656, 38.0292) -> (-35.8737, 38.1992)
  line L27 (-35.4577, 37.8588) -> (-35.6656, 38.0292)
  line L28 (-35.25, 37.688) -> (-35.4577, 37.8588)
  line L29 (-35.0425, 37.5167) -> (-35.25, 37.688)
  line L30 (-34.8352, 37.3451) -> (-35.0425, 37.5167)
  line L31 (-34.6282, 37.173) -> (-34.8352, 37.3451)
  line L32 (-34.4215, 37.0006) -> (-34.6282, 37.173)
  line L33 (-34.215, 36.8278) -> (-34.4215, 37.0006)
  line L34 (-34.0088, 36.6547) -> (-34.215, 36.8278)
  line L35 (-33.8028, 36.4812) -> (-34.0088, 36.6547)
  line L36 (-33.5972, 36.3074) -> (-33.8028, 36.4812)
  line L37 (-33.392, 36.1333) -> (-33.5972, 36.3074)
  line L38 (-33.187, 35.9589) -> (-33.392, 36.1333)
  line L39 (-32.9825, 35.7842) -> (-33.187, 35.9589)
  line L40 (-32.7783, 35.6093) -> (-32.9825, 35.7842)
  line L41 (-32.5745, 35.434) -> (-32.7783, 35.6093)
  line L42 (-32.3711, 35.2584) -> (-32.5745, 35.434)
  line L43 (-32.1682, 35.0826) -> (-32.3711, 35.2584)
  line L44 (-31.9657, 34.9065) -> (-32.1682, 35.0826)
  line L45 (-31.7637, 34.7302) -> (-31.9657, 34.9065)
  line L46 (-31.5623, 34.5535) -> (-31.7637, 34.7302)
  line L47 (-31.3613, 34.3766) -> (-31.5623, 34.5535)
  line L48 (-31.1609, 34.1994) -> (-31.3613, 34.3766)
  line L49 (-30.9611, 34.0219) -> (-31.1609, 34.1994)
  line L50 (-30.7619, 33.8442) -> (-30.9611, 34.0219)
  line L51 (-30.5634, 33.6662) -> (-30.7619, 33.8442)
  line L52 (-30.3654, 33.4878) -> (-30.5634, 33.6662)
  line L53 (-30.1682, 33.3092) -> (-30.3654, 33.4878)
  line L54 (-29.9717, 33.1303) -> (-30.1682, 33.3092)
  line L55 (-29.7759, 32.9511) -> (-29.9717, 33.1303)
  line L56 (-29.5809, 32.7715) -> (-29.7759, 32.9511)
  line L57 (-29.3866, 32.5916) -> (-29.5809, 32.7715)
  line L58 (-29.1932, 32.4114) -> (-29.3866, 32.5916)
  line L59 (-29.0007, 32.2308) -> (-29.1932, 32.4114)
  line L60 (-28.809, 32.0499) -> (-29.0007, 32.2308)
  line L61 (-28.6182, 31.8686) -> (-28.809, 32.0499)
  line L62 (-28.4284, 31.6869) -> (-28.6182, 31.8686)
  line L63 (-28.2395, 31.5048) -> (-28.4284, 31.6869)
  line L64 (-28.0516, 31.3224) -> (-28.2395, 31.5048)
  line L65 (-27.8647, 31.1395) -> (-28.0516, 31.3224)
  line L66 (-27.6789, 30.9562) -> (-27.8647, 31.1395)
  line L67 (-27.4942, 30.7724) -> (-27.6789, 30.9562)
  line L68 (-27.3106, 30.5882) -> (-27.4942, 30.7724)
  line L69 (-27.1281, 30.4035) -> (-27.3106, 30.5882)
  line L70 (-26.9468, 30.2184) -> (-27.1281, 30.4035)
  line L71 (-26.7667, 30.0327) -> (-26.9468, 30.2184)
  line L72 (-26.5878, 29.8465) -> (-26.7667, 30.0327)
  line L73 (-26.4102, 29.6599) -> (-26.5878, 29.8465)
  line L74 (-26.2338, 29.4727) -> (-26.4102, 29.6599)
  line L75 (-26.0588, 29.2849) -> (-26.2338, 29.4727)
  line L76 (-25.8851, 29.0966) -> (-26.0588, 29.2849)
  line L77 (-25.7127, 28.9078) -> (-25.8851, 29.0966)
  line L78 (-25.5418, 28.7183) -> (-25.7127, 28.9078)
  line L79 (-25.3723, 28.5283) -> (-25.5418, 28.7183)
  line L80 (-25.2042, 28.3376) -> (-25.3723, 28.5283)
  line L81 (-25.0376, 28.1464) -> (-25.2042, 28.3376)
  line L82 (-24.8725, 27.9545) -> (-25.0376, 28.1464)
  line L83 (-24.7089, 27.762) -> (-24.8725, 27.9545)
  line L84 (-24.5469, 27.5688) -> (-24.7089, 27.762)
  line L85 (-24.3864, 27.375) -> (-24.5469, 27.5688)
  line L86 (-24.2275, 27.1805) -> (-24.3864, 27.375)
  line L87 (-24.0703, 26.9854) -> (-24.2275, 27.1805)
  line L88 (-23.9146, 26.7895) -> (-24.0703, 26.9854)
  line L89 (-23.7607, 26.593) -> (-23.9146, 26.7895)
  line L90 (-23.6084, 26.3958) -> (-23.7607, 26.593)
  line L91 (-23.4578, 26.1978) -> (-23.6084, 26.3958)
  line L92 (-23.3089, 25.9992) -> (-23.4578, 26.1978)
  line L93 (-23.1618, 25.7998) -> (-23.3089, 25.9992)
  line L94 (-23.0164, 25.5997) -> (-23.1618, 25.7998)
  line L95 (-22.8728, 25.3988) -> (-23.0164, 25.5997)
  line L96 (-22.7309, 25.1972) -> (-22.8728, 25.3988)
  line L97 (-22.5909, 24.9949) -> (-22.7309, 25.1972)
  line L98 (-22.4527, 24.7917) -> (-22.5909, 24.9949)
  line L99 (-22.3163, 24.5879) -> (-22.4527, 24.7917)
  line L100 (-22.1817, 24.3832) -> (-22.3163, 24.5879)
  line L101 (-22.049, 24.1778) -> (-22.1817, 24.3832)
  line L102 (-21.9182, 23.9716) -> (-22.049, 24.1778)
  line L103 (-21.7892, 23.7646) -> (-21.9182, 23.9716)
  line L104 (-21.6622, 23.5568) -> (-21.7892, 23.7646)
  line L105 (-21.537, 23.3482) -> (-21.6622, 23.5568)
  line L106 (-21.4137, 23.1388) -> (-21.537, 23.3482)
  line L107 (-21.2923, 22.9286) -> (-21.4137, 23.1388)
  line L108 (-21.1728, 22.7176) -> (-21.2923, 22.9286)
  line L109 (-21.0553, 22.5058) -> (-21.1728, 22.7176)
  line L110 (-20.9397, 22.2931) -> (-21.0553, 22.5058)
  line L111 (-20.8259, 22.0796) -> (-20.9397, 22.2931)
  line L112 (-20.7142, 21.8653) -> (-20.8259, 22.0796)
  line L113 (-20.6043, 21.6502) -> (-20.7142, 21.8653)
  line L114 (-20.4964, 21.4342) -> (-20.6043, 21.6502)
  line L115 (-20.3904, 21.2174) -> (-20.4964, 21.4342)
  line L116 (-20.2863, 20.9997) -> (-20.3904, 21.2174)
  line L117 (-20.1842, 20.7812) -> (-20.2863, 20.9997)
  line L118 (-20.0839, 20.5618) -> (-20.1842, 20.7812)
  line L119 (-19.9856, 20.3416) -> (-20.0839, 20.5618)
  line L120 (-19.8892, 20.1205) -> (-19.9856, 20.3416)
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extrude "Extrude1" new body sketch "Roller compensated replaceable cam" along normal blind 8 bodies "P08 Cam 3 gates - stable endpoints"
work_plane "WorkPlane2" AlongDistance 6.9 ExtraOffset 0
sketch "Cam screw clearance" plane through (6.9, 0, 0) normal (1, 0, 0) x axis (0, 0, -1)
  circle C1 centre (-39.5442, 25.4558) radius 1.7
extrude "Extrude2" cut sketch "Cam screw clearance" along normal blind 8.2
work_plane "WorkPlane3" AlongDistance 12 ExtraOffset 0
sketch "Cam head recess" plane through (12, 0, 0) normal (1, 0, 0) x axis (0, 0, -1)
  circle C1 centre (-39.5442, 25.4558) radius 3.1
extrude "Extrude3" cut sketch "Cam head recess" along normal blind 3.1
work_plane "WorkPlane4" AlongDistance 6.9 ExtraOffset 0
sketch "Cam screw clearance (1)" plane through (6.9, 0, 0) normal (1, 0, 0) x axis (0, 0, -1)
  circle C1 centre (-29, 0) radius 1.7
extrude "Extrude4" cut sketch "Cam screw clearance (1)" along normal blind 8.2
work_plane "WorkPlane5" AlongDistance 12 ExtraOffset 0
sketch "Cam head recess (1)" plane through (12, 0, 0) normal (1, 0, 0) x axis (0, 0, -1)
  circle C1 centre (-29, 0) radius 3.1
extrude "Extrude5" cut sketch "Cam head recess (1)" along normal blind 3.1
work_plane "WorkPlane6" AlongDistance 6.9 ExtraOffset 0
sketch "Cam screw clearance (2)" plane through (6.9, 0, 0) normal (1, 0, 0) x axis (0, 0, -1)
  circle C1 centre (-39.5442, -25.4558) radius 1.7
extrude "Extrude6" cut sketch "Cam screw clearance (2)" along normal blind 8.2
work_plane "WorkPlane7" AlongDistance 12 ExtraOffset 0
sketch "Cam head recess (2)" plane through (12, 0, 0) normal (1, 0, 0) x axis (0, 0, -1)
  circle C1 centre (-39.5442, -25.4558) radius 3.1
extrude "Extrude7" cut sketch "Cam head recess (2)" along normal blind 3.1
work_plane "WorkPlane1" AlongDistance 0 ExtraOffset 0
sketch "Palm grip smooth contour" plane through (0, 0, 0) normal (1, 0, 0) x axis (0, 0, -1)
  curve K1 (-225, 0) -> (-165, 12)
  line L1 (-225, 0) -> (-165, 0)
  line L2 (-165, 12) -> (-165, 0)
revolve "Revolve1" sketch "Palm grip smooth contour" AlongAngle 360 bodies "P09 Grip insert half"
work_plane "WorkPlane2" AlongDistance 0 ExtraOffset 0
sketch "Split on print bed face" plane through (0, 0, 0) normal (1, 0, 0) x axis (0, 0, -1)
  line L1 (-160, 30) -> (-160, -30)
  line L2 (-230, 30) -> (-160, 30)
  line L3 (-230, -30) -> (-230, 30)
  line L4 (-160, -30) -> (-230, -30)
extrude "Extrude1" cut sketch "Split on print bed face" along normal blind 30
work_plane "WorkPlane3" AlongDistance -7.2 ExtraOffset 0
sketch "Keyed stem socket" plane through (-7.2, 0, 0) normal (1, 0, 0) x axis (0, 0, -1)
  line L1 (-164, 7.2) -> (-164, -7.2)
  line L2 (-196, 7.2) -> (-164, 7.2)
  line L3 (-196, -7.2) -> (-196, 7.2)
  line L4 (-164, -7.2) -> (-196, -7.2)
extrude "Extrude2" cut sketch "Keyed stem socket" along normal blind 14.4
work_plane "WorkPlane4" AlongDistance -13.9 ExtraOffset 0
sketch "M3 grip heat set" plane through (-13.9, 0, 0) normal (1, 0, 0) x axis (0, 0, -1)
  circle C1 centre (-180, 0) radius 2
extrude "Extrude3" cut sketch "M3 grip heat set" along normal blind 6.8
work_plane "WorkPlane5" AlongDistance -13.9 ExtraOffset 0
sketch "M3 grip heat set (1)" plane through (-13.9, 0, 0) normal (1, 0, 0) x axis (0, 0, -1)
  circle C1 centre (-190, 0) radius 2
extrude "Extrude4" cut sketch "M3 grip heat set (1)" along normal blind 6.8
work_plane "WorkPlane1" AlongDistance 0 ExtraOffset 0
sketch "Palm grip smooth contour" plane through (0, 0, 0) normal (1, 0, 0) x axis (0, 0, -1)
  curve K1 (-225, 0) -> (-165, 12)
  line L1 (-225, 0) -> (-165, 0)
  line L2 (-165, 12) -> (-165, 0)
revolve "Revolve1" sketch "Palm grip smooth contour" AlongAngle 360 bodies "P10 Grip screw half"
work_plane "WorkPlane2" AlongDistance -30 ExtraOffset 0
sketch "Split on print bed face" plane through (-30, 0, 0) normal (1, 0, 0) x axis (0, 0, -1)
  line L1 (-160, 30) -> (-160, -30)
  line L2 (-230, 30) -> (-160, 30)
  line L3 (-230, -30) -> (-230, 30)
  line L4 (-160, -30) -> (-230, -30)
extrude "Extrude1" cut sketch "Split on print bed face" along normal blind 30
work_plane "WorkPlane3" AlongDistance -7.2 ExtraOffset 0
sketch "Keyed stem socket" plane through (-7.2, 0, 0) normal (1, 0, 0) x axis (0, 0, -1)
  line L1 (-164, 7.2) -> (-164, -7.2)
  line L2 (-196, 7.2) -> (-164, 7.2)
  line L3 (-196, -7.2) -> (-196, 7.2)
  line L4 (-164, -7.2) -> (-196, -7.2)
extrude "Extrude2" cut sketch "Keyed stem socket" along normal blind 14.4
work_plane "WorkPlane4" AlongDistance -0.1 ExtraOffset 0
sketch "Grip screw bore" plane through (-0.1, 0, 0) normal (1, 0, 0) x axis (0, 0, -1)
  circle C1 centre (-180, 0) radius 1.7
extrude "Extrude3" cut sketch "Grip screw bore" along normal blind 26
work_plane "WorkPlane5" AlongDistance 12.5 ExtraOffset 0
sketch "Recessed grip screw head" plane through (12.5, 0, 0) normal (1, 0, 0) x axis (0, 0, -1)
  circle C1 centre (-180, 0) radius 3.1
extrude "Extrude4" cut sketch "Recessed grip screw head" along normal blind 14
work_plane "WorkPlane6" AlongDistance -0.1 ExtraOffset 0
sketch "Grip screw bore (1)" plane through (-0.1, 0, 0) normal (1, 0, 0) x axis (0, 0, -1)
  circle C1 centre (-190, 0) radius 1.7
extrude "Extrude5" cut sketch "Grip screw bore (1)" along normal blind 26
work_plane "WorkPlane7" AlongDistance 12.5 ExtraOffset 0
sketch "Recessed grip screw head (1)" plane through (12.5, 0, 0) normal (1, 0, 0) x axis (0, 0, -1)
  circle C1 centre (-190, 0) radius 3.1
extrude "Extrude6" cut sketch "Recessed grip screw head (1)" along normal blind 14
work_plane "WorkPlane1" AlongDistance 4 ExtraOffset 0
sketch "First strong flat cheek" plane through (4, 0, 0) normal (1, 0, 0) x axis (0, 0, -1)
  line L1 (-6, -5) -> (-6, -61)
  line L2 (-7, 0) -> (-6, -5)
  line L3 (-17, 0) -> (-7, 0)
  line L4 (-18, -5) -> (-17, 0)
  line L5 (-18, -61) -> (-18, -5)
  line L6 (-6, -61) -> (-18, -61)
extrude "Extrude1" new body sketch "First strong flat cheek" along normal blind 3 bodies "P11 Forked roller follower"
work_plane "WorkPlane2" AlongDistance 4 ExtraOffset 0
sketch "Spring tail bridge" plane through (4, 0, 0) normal (1, 0, 0) x axis (0, 0, -1)
  line L1 (-6, -49) -> (-6, -61)
  line L2 (-18, -49) -> (-6, -49)
  line L3 (-18, -61) -> (-18, -49)
  line L4 (-6, -61) -> (-18, -61)
extrude "Extrude2" add sketch "Spring tail bridge" along normal blind 16
work_plane "WorkPlane3" AlongDistance 17 ExtraOffset 0
sketch "Second supporting cheek" plane through (17, 0, 0) normal (1, 0, 0) x axis (0, 0, -1)
  line L1 (-6, -5) -> (-6, -61)
  line L2 (-7, 0) -> (-6, -5)
  line L3 (-17, 0) -> (-7, 0)
  line L4 (-18, -5) -> (-17, 0)
  line L5 (-18, -61) -> (-18, -5)
  line L6 (-6, -61) -> (-18, -61)
extrude "Extrude3" add sketch "Second supporting cheek" along normal blind 3
work_plane "WorkPlane4" AlongDistance 4 ExtraOffset 0
sketch "Rounded roller cheek" plane through (4, 0, 0) normal (1, 0, 0) x axis (0, 0, -1)
  circle C1 centre (-12, 0) radius 6
extrude "Extrude4" add sketch "Rounded roller cheek" along normal blind 3
work_plane "WorkPlane5" AlongDistance 17 ExtraOffset 0
sketch "Rounded roller cheek (1)" plane through (17, 0, 0) normal (1, 0, 0) x axis (0, 0, -1)
  circle C1 centre (-12, 0) radius 6
extrude "Extrude5" add sketch "Rounded roller cheek (1)" along normal blind 3
work_plane "WorkPlane6" AlongDistance 3.9 ExtraOffset 0
sketch "Smooth pivot sleeve bore" plane through (3.9, 0, 0) normal (1, 0, 0) x axis (0, 0, -1)
  circle C1 centre (-12, -35) radius 4.15
extrude "Extrude6" cut sketch "Smooth pivot sleeve bore" along normal blind 16.2
work_plane "WorkPlane7" AlongDistance 3.9 ExtraOffset 0
sketch "Roller axle holes" plane through (3.9, 0, 0) normal (1, 0, 0) x axis (0, 0, -1)
  circle C1 centre (-12, 0) radius 1.7
extrude "Extrude7" cut sketch "Roller axle holes" along normal blind 16.2
work_plane "WorkPlane8" AlongDistance 3.9 ExtraOffset 0
sketch "Roller M3 nut recess" plane through (3.9, 0, 0) normal (1, 0, 0) x axis (0, 0, -1)
  line L1 (-14.9, 1.6743) -> (-12, 3.3486)
  line L2 (-14.9, -1.6743) -> (-14.9, 1.6743)
  line L3 (-12, -3.3486) -> (-14.9, -1.6743)
  line L4 (-9.1, -1.6743) -> (-12, -3.3486)
  line L5 (-9.1, 1.6743) -> (-9.1, -1.6743)
  line L6 (-12, 3.3486) -> (-9.1, 1.6743)
extrude "Extrude8" cut sketch "Roller M3 nut recess" along normal blind 1.6
work_plane "WorkPlane9" AlongDistance 18 ExtraOffset 0
sketch "Spring tail locating pilot" plane through (0, 0, 18) normal (0, 0, 1) x axis (1, 0, 0)
  circle C1 centre (12, -55) radius 1.8
extrude "Extrude9" add sketch "Spring tail locating pilot" along normal blind 2
work_plane "WorkPlane1" AlongDistance -24 ExtraOffset 0
sketch "Captured spring reaction block" plane through (-24, 0, 0) normal (1, 0, 0) x axis (0, 0, -1)
  line L1 (-38, -44) -> (-38, -66)
  line L2 (-52, -44) -> (-38, -44)
  line L3 (-52, -66) -> (-52, -44)
  line L4 (-38, -66) -> (-52, -66)
extrude "Extrude1" new body sketch "Captured spring reaction block" along normal blind 48
work_plane "WorkPlane2" AlongDistance -24.1 ExtraOffset 0
sketch "Left M3 insert with screw tip relief" plane through (-24.1, 0, 0) normal (1, 0, 0) x axis (0, 0, -1)
  circle C1 centre (-44, -59) radius 2
extrude "Extrude2" cut sketch "Left M3 insert with screw tip relief" along normal blind 8.8
work_plane "WorkPlane3" AlongDistance 15.3 ExtraOffset 0
sketch "Right M3 insert with screw tip relief" plane through (15.3, 0, 0) normal (1, 0, 0) x axis (0, 0, -1)
  circle C1 centre (-44, -59) radius 2
extrude "Extrude3" cut sketch "Right M3 insert with screw tip relief" along normal blind 8.8
work_plane "WorkPlane4" AlongDistance -24.1 ExtraOffset 0
sketch "Left M3 insert with screw tip relief (1)" plane through (-24.1, 0, 0) normal (1, 0, 0) x axis (0, 0, -1)
  circle C1 centre (-44, -51) radius 2
extrude "Extrude4" cut sketch "Left M3 insert with screw tip relief (1)" along normal blind 8.8
work_plane "WorkPlane5" AlongDistance 15.3 ExtraOffset 0
sketch "Right M3 insert with screw tip relief (1)" plane through (15.3, 0, 0) normal (1, 0, 0) x axis (0, 0, -1)
  circle C1 centre (-44, -51) radius 2
extrude "Extrude5" cut sketch "Right M3 insert with screw tip relief (1)" along normal blind 8.8
work_plane "WorkPlane6" AlongDistance 37.9 ExtraOffset 0
sketch "M4 preload adjuster" plane through (0, 0, 37.9) normal (0, 0, 1) x axis (1, 0, 0)
  circle C1 centre (12, -55) radius 2.2
extrude "Extrude6" cut sketch "M4 preload adjuster" along normal blind 14.2
work_plane "WorkPlane7" AlongDistance 37.9 ExtraOffset 0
